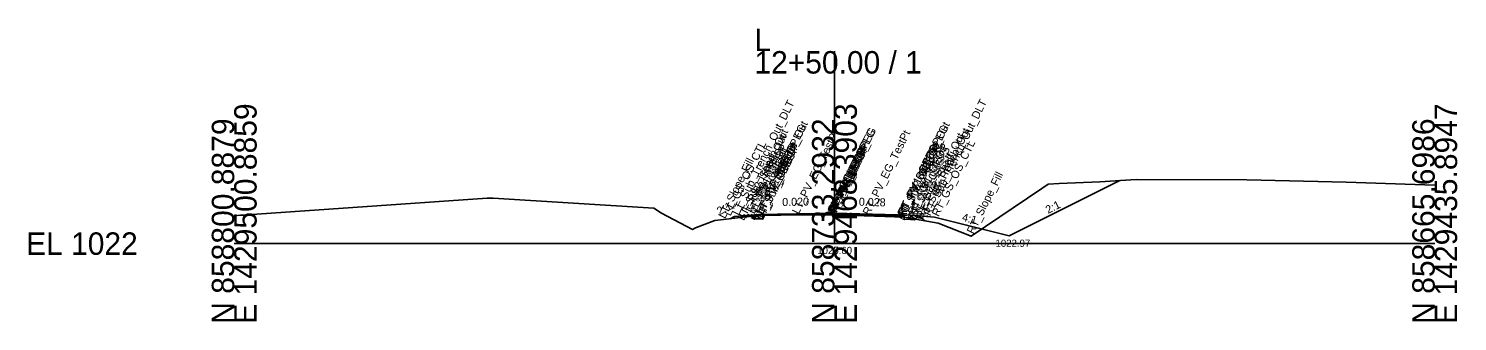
# Model space of a CAD drawing. Extents: x -26 to 153, y -10 to 13058.
# Drawn here: x -25.7 to 152.8, y 1990.3 to 2026.8 of the extents above; entities that cross this region are included whole.
import ezdxf

# ---------------------------------------------------------------- set-up
doc = ezdxf.new("R2010")
doc.units = 0
for name, color, linetype in [('Default', 7, 'Continuous'), ('Exist Cross Section Cell', 7, 'Continuous'), ('Exist XS Center Line Elevation Label', 7, 'Continuous'), ('Exist XS Ground Line', 7, 'Continuous'), ('Prop CMT Pvmt Course 1', 7, 'Continuous'), ('Prop CMT Pvmt Course 1 Wedge', 7, 'Continuous'), ('Prop CMT Pvmt Surface', 7, 'Continuous'), ('Prop CMT Pvmt Surface Shoulder', 7, 'Continuous'), ('Prop CMT Pvmt Wedge Surface 1', 7, 'Continuous'), ('Prop CMT Shld Paved Course 1', 7, 'Continuous'), ('Prop CMT Slope Grass', 7, 'Continuous'), ('Prop CMT Subgrade Earthwork', 7, 'Continuous'), ('Prop XS Dump Level', 7, 'Continuous'), ('Prop XS SE Text', 7, 'Continuous'), ('Prop XS Side Slope Text', 7, 'Continuous')]:
    doc.layers.add(name, color=color, linetype=linetype)

msp = doc.modelspace()

# ---------------------------------------------------------------- linework, layer by layer
at = {"layer": 'Exist Cross Section Cell'}
for p, q in [((75, 2000), (75, 2024)), ((0, 2000), (75, 2000)), ((75, 2000), (150, 2000))]:
    msp.add_line(p, q, dxfattribs=at)
at = {"layer": 'Exist XS Ground Line'}
msp.add_lwpolyline([(0, 2003.48), (0.77, 2003.54), (1.21, 2003.56), (1.64, 2003.58), (17.83, 2004.7), (31.6, 2005.65), (32.36, 2005.65), (52.42, 2004.43), (53.37, 2003.81), (57.27, 2001.77), (57.64, 2001.96), (60.06, 2002.87), (61.13, 2003.01), (66.05, 2003.59), (72.3, 2003.6), (74.89, 2003.6), (81.28, 2003.38), (83.72, 2003.28), (87.95, 2002.54), (92.07, 2000.91), (100.93, 2006.89), (101.72, 2007.42), (103.09, 2007.5), (108.16, 2007.71), (112.69, 2008), (126.54, 2007.94), (138.94, 2007.68), (150, 2007.28)], dxfattribs=at)
at = {"layer": 'Prop CMT Pvmt Course 1'}
for points in [[(75, 2003.81), (65.5, 2003.62)], [(65.5, 2003.62), (65.5, 2003.08)], [(66.05, 2003.51), (75, 2003.69)], [(66.05, 2003.09), (66.05, 2003.51)], [(75, 2003.27), (75, 2003.81)], [(75, 2003.81), (84.5, 2003.55)], [(75, 2003.27), (75, 2003.81)], [(75, 2003.69), (75, 2003.27), (75, 2003.27)], [(83.72, 2003.44), (75, 2003.69)], [(75, 2003.69), (75, 2003.27), (75, 2003.27)], [(83.72, 2003.03), (83.72, 2003.44)], [(84.5, 2003.55), (84.5, 2003)], [(65.5, 2003.08), (66.05, 2003.09)], [(84.5, 2003), (83.72, 2003.03)]]:
    msp.add_lwpolyline(points, dxfattribs=at)
at = {"layer": 'Prop CMT Pvmt Course 1 Wedge'}
for points in [[(70.76, 2003.6), (72.3, 2003.63)], [(75, 2003.6), (74.89, 2003.6), (72.3, 2003.6), (70.76, 2003.6)], [(72.3, 2003.63), (74.89, 2003.68), (75, 2003.69)], [(75, 2003.69), (75, 2003.6)], [(75, 2003.69), (81.28, 2003.51), (83.72, 2003.44)], [(75, 2003.6), (75, 2003.69)], [(83.72, 2003.28), (81.28, 2003.38), (75, 2003.6)], [(83.72, 2003.44), (83.72, 2003.28), (83.72, 2003.28)]]:
    msp.add_lwpolyline(points, dxfattribs=at)
at = {"layer": 'Prop CMT Pvmt Surface'}
for points in [[(75, 2003.81), (65.5, 2003.62)], [(75, 2003.81), (84.5, 2003.55)]]:
    msp.add_lwpolyline(points, dxfattribs=at)
at = {"layer": 'Prop CMT Pvmt Surface Shoulder'}
for points in [[(65.5, 2003.62), (65.5, 2003.62)], [(84.5, 2003.55), (84.5, 2003.55)]]:
    msp.add_lwpolyline(points, dxfattribs=at)
at = {"layer": 'Prop CMT Pvmt Wedge Surface 1'}
for points in [[(65.5, 2003.08), (65.5, 2003.62)], [(75, 2003.69), (66.05, 2003.51)], [(66.05, 2003.51), (66.05, 2003.09)], [(75, 2003.69), (83.72, 2003.44)], [(83.72, 2003.44), (83.72, 2003.03)], [(84.5, 2003), (84.5, 2003.55)], [(66.05, 2003.09), (65.5, 2003.08)], [(83.72, 2003.03), (84.5, 2003)]]:
    msp.add_lwpolyline(points, dxfattribs=at)
at = {"layer": 'Prop CMT Shld Paved Course 1'}
for points in [[(65.5, 2003.62), (64.95, 2003.07)], [(65.5, 2003.62), (65.5, 2003.62)], [(65.5, 2003.08), (65.5, 2003.62)], [(84.5, 2003.55), (84.5, 2003.55)], [(84.5, 2003.55), (85.05, 2002.99)], [(84.5, 2003), (84.5, 2003.55)], [(64.95, 2003.07), (65.5, 2003.08)], [(85.05, 2002.99), (84.5, 2003)]]:
    msp.add_lwpolyline(points, dxfattribs=at)
at = {"layer": 'Prop CMT Slope Grass'}
for p, q in [((96.85, 2000.97), (110.65, 2007.87)), ((87.5, 2003.31), (96.85, 2000.97))]:
    msp.add_line(p, q, dxfattribs=at)
for points in [[(65.5, 2003.62), (62.5, 2003.38), (61.95, 2003.11)], [(84.5, 2003.55), (87.5, 2003.31)]]:
    msp.add_lwpolyline(points, dxfattribs=at)
at = {"layer": 'Prop CMT Subgrade Earthwork'}
for points in [[(64.95, 2003.07), (64.48, 2003.54)], [(66.05, 2003.09), (66.07, 2003.59)], [(83.72, 2003.03), (83.7, 2003.28)], [(85.05, 2002.99), (85.52, 2003.46)], [(65.5, 2003.08), (64.95, 2003.07)], [(66.05, 2003.09), (65.5, 2003.08)], [(83.72, 2003.03), (84.5, 2003)], [(84.5, 2003), (85.05, 2002.99)]]:
    msp.add_lwpolyline(points, dxfattribs=at)

# ---------------------------------------------------------------- texts
at = {"layer": 'Default'}
for s, height, p in [('-', 0.0001, (0, 2000)), ('1022.97', 0.9, (95.12, 1999.6))]:
    msp.add_text(s, height=height, dxfattribs=at).set_placement(p)
at = {"layer": 'Exist Cross Section Cell'}
for s, p in [('L', (65, 2024)), ('12+50.00 / 1', (65, 2021.2)), ('EL 1022', (-26, 1998.6))]:
    msp.add_text(s, height=2.8, dxfattribs=at).set_placement(p)
for s, p in [('E 1429500.8859', (2.8, 1990)), ('E 1429468.3903', (77.8, 1990)), ('E 1429435.8947', (152.8, 1990)), ('N 858800.8879', (0, 1990)), ('N 858733.2932', (75, 1990)), ('N 858665.6986', (150, 1990))]:
    msp.add_text(s, height=2.8, rotation=90, dxfattribs=at).set_placement(p)
at = {"layer": 'Exist XS Center Line Elevation Label'}
msp.add_text('1025.60', height=0.9, dxfattribs=at).set_placement((72.85, 1998.7))
msp.add_text('1025.60', height=0.9, dxfattribs=at).set_placement((72.85, 1998.7))
msp.add_text('1025.60', height=0.9, dxfattribs=at).set_placement((72.85, 1998.7))
at = {"layer": 'Prop XS Dump Level'}
for s, p in [('LT_Sub_Trench_Out_DLT', (63.03, 2003.45)), ('RT_Sub_Trench_Out_DLT', (86.97, 2003.37)), ('LT_Sub_Trench_Out', (63.69, 2002.79)), ('LT_PV_OEEOP_EG', (66.05, 2003.59)), ('LT_PV_Sub_Tie_Out', (66.07, 2003.59)), ('LT_PV_EG_TestPt', (70.53, 2003.6)), ('RT_PV_IEEOP_EG', (75, 2003.6)), ('LT_PV_IEEOP_EG', (75, 2003.6)), ('RT_PV_EG_TestPt', (79.36, 2003.44)), ('RT_PV_Sub_Tie_Out', (83.7, 2003.28)), ('RT_PV_OEEOP_EG', (83.72, 2003.28)), ('RT_Sub_Trench_Out', (86.31, 2002.71)), ('LT_GS_OS_CTL', (62, 2003.37)), ('LT_PS2_Shelf_Out', (63.95, 2003.05)), ('LT_PV1_OEOT', (65, 2003.61)), ('LT_PS1_OEOP', (65, 2003.61)), ('LT_PV1_OEEOP', (66.05, 2003.51)), ('LT_PV2_OEEOP', (66.05, 2003.09)), ('LT_Sub_OEEOP', (66.05, 2002.84)), ('RT_PV1_IEEOP', (75, 2003.69)), ('LT_PV1_IEEOP', (75, 2003.69)), ('RT_PV2_IEEOP', (75, 2003.27)), ('LT_PV2_IEEOP', (75, 2003.27)), ('RT_PV1_OEEOP', (83.72, 2003.44)), ('RT_PV2_OEEOP', (83.72, 2003.03)), ('RT_Sub_OEEOP', (83.72, 2002.78)), ('RT_PV1_OEOT', (85, 2003.53)), ('RT_PS1_OEOP', (85, 2003.53)), ('RT_PS2_Shelf_Out', (86.05, 2002.97)), ('RT_GS_OS_CTL', (88, 2003.29)), ('LT_Slope_Fill', (61.33, 2003.03)), ('LT_PS2_OEOP', (64.45, 2003.06)), ('LT_PV2_OEOT', (65, 2003.07)), ('LT_Sub_OEOT', (65, 2002.82)), ('RT_PV2_OEOT', (85, 2002.99)), ('RT_Sub_OEOT', (85, 2002.74)), ('RT_PS2_OEOP', (85.55, 2002.98)), ('PV1_PGL', (75, 2003.81)), ('PV2_PGL', (75, 2003.27)), ('RT_Slope_Fill', (92.37, 2001.11))]:
    msp.add_text(s, height=1, rotation=63.5833, dxfattribs=at).set_placement(p)
at = {"layer": 'Prop XS SE Text'}
for s, rotation, p in [('0.020', 1.1458, (68.48, 2004.68)), ('0.028', 358.3961, (78.04, 2004.73))]:
    msp.add_text(s, height=1, rotation=rotation, dxfattribs=at).set_placement(p)
at = {"layer": 'Prop XS Side Slope Text'}
for s, rotation, p in [('2:1', 26.565, (60.62, 2003.52)), ('2:1', 26.5651, (101.69, 2003.69)), ('4:1', 345.9638, (90.87, 2002.86))]:
    msp.add_text(s, height=1, rotation=rotation, dxfattribs=at).set_placement(p)

doc.saveas('drawing.dxf')
